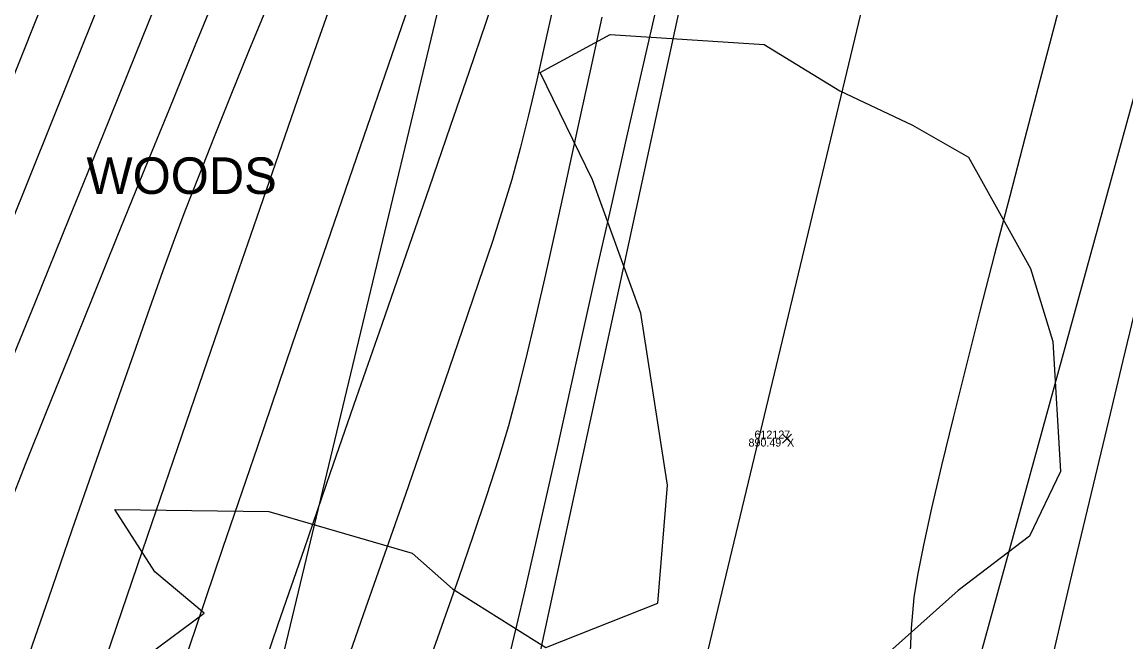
# Model space of a CAD drawing. Extents: x 1957117 to 1971063, y 701601 to 715861.
# Drawn here: x 1963376.25 to 1963424.5, y 706387.49 to 706414.59 of the extents above; entities that cross this region are included whole.
import ezdxf

# ---------------------------------------------------------------- set-up
doc = ezdxf.new("R2010")
doc.units = 0
for name, color, linetype in [('AP_X_Lights', 7, 'Continuous'), ('DT_X_Break_Line', 7, 'Continuous'), ('DT_X_Contour_Major', 7, 'Continuous'), ('DT_X_Contour_Minor', 7, 'Continuous'), ('GE_X_CL_20', 7, 'Continuous'), ('HY_X_Water_Edge', 7, 'Continuous'), ('PV_P_Shoulder', 7, 'Continuous'), ('RS_Raster1', 7, 'Continuous'), ('RW_X_Esmt_RR', 7, 'Continuous'), ('SC_Scratch1', 7, 'Continuous'), ('SC_Shading5', 7, 'Continuous'), ('VG_X_Text', 7, 'Continuous'), ('VG_X_Tree_Line_Rt', 7, 'Continuous')]:
    doc.layers.add(name, color=color, linetype=linetype)

msp = doc.modelspace()

# ---------------------------------------------------------------- linework, layer by layer
at = {"layer": 'AP_X_Lights'}
for p, q in [((1963409.494, 706396.183), (1963409.882, 706396.573)), ((1963409.494, 706396.573), (1963409.882, 706396.183))]:
    msp.add_line(p, q, dxfattribs=at)
at = {"layer": 'DT_X_Break_Line'}
for points in [[(1963248.355, 705747.376), (1963261.829, 705795.923), (1963267.581, 705840.559), (1963287.153, 705892.264), (1963291.083, 705944.763), (1963301.574, 705996.211), (1963311.528, 706039.027), (1963334.717, 706086.75), (1963331.957, 706106.508), (1963348.786, 706182.796), (1963365.664, 706223.934), (1963373.462, 706281.461), (1963387.853, 706330.217), (1963397.264, 706379.501), (1963407.696, 706427.592), (1963426.755, 706477.16), (1963442.136, 706524.014), (1963446.007, 706569.971), (1963489.391, 706666.839), (1963500.526, 706701.536)], [(1963509.92, 706697.686), (1963502.832, 706666.547), (1963464.625, 706568.104), (1963439.113, 706472.593), (1963428.782, 706425.675), (1963415.739, 706378.185), (1963398.991, 706327.191), (1963392.393, 706279.173), (1963377.9, 706227.719), (1963369.87, 706175.335), (1963345.874, 706098.69), (1963341.112, 706081.071), (1963328.328, 706036.261), (1963311.276, 705989.111), (1963300.503, 705940.076), (1963293.199, 705890.767), (1963276.592, 705844.792), (1963268.336, 705791.927), (1963260.722, 705745.719)]]:
    msp.add_lwpolyline(points, dxfattribs=at)
at = {"layer": 'DT_X_Contour_Major'}
for points in [[(1963387.31, 706442.991), (1963386.479, 706440.327), (1963385.732, 706437.97), (1963385.082, 706435.973), (1963384.545, 706434.39), (1963383.905, 706432.647), (1963382.92, 706430.067), (1963381.625, 706426.744), (1963380.061, 706422.771), (1963378.264, 706418.242), (1963376.274, 706413.248), (1963374.129, 706407.883), (1963371.866, 706402.241), (1963369.524, 706396.415), (1963367.142, 706390.496), (1963364.757, 706384.58)], [(1963387.31, 706442.991), (1963386.479, 706440.327), (1963385.732, 706437.97), (1963385.082, 706435.973), (1963384.545, 706434.39), (1963383.905, 706432.647), (1963382.92, 706430.067), (1963381.625, 706426.744), (1963380.061, 706422.771), (1963378.264, 706418.242), (1963376.274, 706413.248), (1963374.129, 706407.883), (1963371.866, 706402.241), (1963369.524, 706396.415), (1963367.142, 706390.496), (1963364.757, 706384.58)], [(1963424.522, 706427.015), (1963424.149, 706425.395), (1963423.812, 706423.96), (1963423.467, 706422.548), (1963423.039, 706420.849), (1963422.539, 706418.904), (1963421.981, 706416.756), (1963421.377, 706414.447), (1963420.741, 706412.018), (1963420.084, 706409.512), (1963419.421, 706406.971), (1963418.763, 706404.436), (1963418.123, 706401.949), (1963417.514, 706399.553), (1963416.95, 706397.29), (1963416.442, 706395.201), (1963416.004, 706393.329), (1963415.648, 706391.716), (1963415.387, 706390.403), (1963415.234, 706389.432), (1963415.11, 706388.084), (1963415.052, 706386.722)], [(1963424.522, 706427.015), (1963424.149, 706425.395), (1963423.812, 706423.96), (1963423.467, 706422.548), (1963423.039, 706420.849), (1963422.539, 706418.904), (1963421.981, 706416.756), (1963421.377, 706414.447), (1963420.741, 706412.018), (1963420.084, 706409.512), (1963419.421, 706406.971), (1963418.763, 706404.436), (1963418.123, 706401.949), (1963417.514, 706399.553), (1963416.95, 706397.29), (1963416.442, 706395.201), (1963416.004, 706393.329), (1963415.648, 706391.716), (1963415.387, 706390.403), (1963415.234, 706389.432), (1963415.11, 706388.084), (1963415.052, 706386.722)], [(1963389.698, 706415.242), (1963388.846, 706412.8), (1963387.864, 706409.974), (1963386.773, 706406.821), (1963385.591, 706403.399), (1963384.34, 706399.765), (1963383.041, 706395.977), (1963381.713, 706392.091), (1963380.376, 706388.166), (1963379.052, 706384.259)], [(1963389.698, 706415.242), (1963388.846, 706412.8), (1963387.864, 706409.974), (1963386.773, 706406.821), (1963385.591, 706403.399), (1963384.34, 706399.765), (1963383.041, 706395.977), (1963381.713, 706392.091), (1963380.376, 706388.166), (1963379.052, 706384.259)], [(1963403.94, 706415.084), (1963403.31, 706412.355), (1963402.674, 706409.561), (1963402.038, 706406.742), (1963401.409, 706403.94), (1963400.796, 706401.194), (1963400.206, 706398.547), (1963399.646, 706396.037), (1963399.125, 706393.707), (1963398.649, 706391.597), (1963398.227, 706389.747), (1963397.866, 706388.199), (1963397.573, 706386.992)], [(1963403.94, 706415.084), (1963403.31, 706412.355), (1963402.674, 706409.561), (1963402.038, 706406.742), (1963401.409, 706403.94), (1963400.796, 706401.194), (1963400.206, 706398.547), (1963399.646, 706396.037), (1963399.125, 706393.707), (1963398.649, 706391.597), (1963398.227, 706389.747), (1963397.866, 706388.199), (1963397.573, 706386.992)]]:
    msp.add_lwpolyline(points, dxfattribs=at)
at = {"layer": 'DT_X_Contour_Minor'}
for points in [[(1963390.055, 706443.837), (1963389.3, 706441.399), (1963388.592, 706439.145), (1963387.942, 706437.114), (1963387.362, 706435.346), (1963386.862, 706433.88), (1963386.308, 706432.363), (1963385.488, 706430.214), (1963384.431, 706427.5), (1963383.166, 706424.291), (1963381.721, 706420.655), (1963380.126, 706416.662), (1963378.409, 706412.381), (1963376.598, 706407.88), (1963374.722, 706403.228), (1963372.81, 706398.494), (1963370.891, 706393.747), (1963368.993, 706389.056), (1963367.145, 706384.49)], [(1963390.055, 706443.837), (1963389.3, 706441.399), (1963388.592, 706439.145), (1963387.942, 706437.114), (1963387.362, 706435.346), (1963386.862, 706433.88), (1963386.308, 706432.363), (1963385.488, 706430.214), (1963384.431, 706427.5), (1963383.166, 706424.291), (1963381.721, 706420.655), (1963380.126, 706416.662), (1963378.409, 706412.381), (1963376.598, 706407.88), (1963374.722, 706403.228), (1963372.81, 706398.494), (1963370.891, 706393.747), (1963368.993, 706389.056), (1963367.145, 706384.49)], [(1963394.717, 706442.917), (1963394.15, 706441.057), (1963393.588, 706439.242), (1963393.036, 706437.494), (1963392.5, 706435.833), (1963391.985, 706434.282), (1963391.498, 706432.861), (1963391.071, 706431.689), (1963390.5, 706430.187), (1963389.799, 706428.391), (1963388.986, 706426.339), (1963388.076, 706424.068), (1963387.086, 706421.616), (1963386.033, 706419.019), (1963384.934, 706416.316), (1963383.803, 706413.543), (1963382.659, 706410.738), (1963381.517, 706407.938), (1963380.393, 706405.18), (1963379.305, 706402.503), (1963378.268, 706399.942), (1963377.3, 706397.536), (1963376.416, 706395.322), (1963375.633, 706393.337)], [(1963394.717, 706442.917), (1963394.15, 706441.057), (1963393.588, 706439.242), (1963393.036, 706437.494), (1963392.5, 706435.833), (1963391.985, 706434.282), (1963391.498, 706432.861), (1963391.071, 706431.689), (1963390.5, 706430.187), (1963389.799, 706428.391), (1963388.986, 706426.339), (1963388.076, 706424.068), (1963387.086, 706421.616), (1963386.033, 706419.019), (1963384.934, 706416.316), (1963383.803, 706413.543), (1963382.659, 706410.738), (1963381.517, 706407.938), (1963380.393, 706405.18), (1963379.305, 706402.503), (1963378.268, 706399.942), (1963377.3, 706397.536), (1963376.416, 706395.322), (1963375.633, 706393.337)], [(1963392.079, 706442.364), (1963391.421, 706440.247), (1963390.794, 706438.257), (1963390.205, 706436.427), (1963389.664, 706434.787), (1963389.18, 706433.371), (1963388.711, 706432.082), (1963388.05, 706430.344), (1963387.217, 706428.203), (1963386.233, 706425.709), (1963385.119, 706422.908), (1963383.893, 706419.848), (1963382.577, 706416.578), (1963381.192, 706413.144), (1963379.756, 706409.596), (1963378.291, 706405.981), (1963376.816, 706402.346), (1963375.352, 706398.74), (1963373.92, 706395.21), (1963372.539, 706391.804), (1963371.23, 706388.571), (1963370.013, 706385.557)], [(1963392.079, 706442.364), (1963391.421, 706440.247), (1963390.794, 706438.257), (1963390.205, 706436.427), (1963389.664, 706434.787), (1963389.18, 706433.371), (1963388.711, 706432.082), (1963388.05, 706430.344), (1963387.217, 706428.203), (1963386.233, 706425.709), (1963385.119, 706422.908), (1963383.893, 706419.848), (1963382.577, 706416.578), (1963381.192, 706413.144), (1963379.756, 706409.596), (1963378.291, 706405.981), (1963376.816, 706402.346), (1963375.352, 706398.74), (1963373.92, 706395.21), (1963372.539, 706391.804), (1963371.23, 706388.571), (1963370.013, 706385.557)], [(1963393.693, 706416.887), (1963392.405, 706413.152), (1963391.019, 706409.128), (1963389.562, 706404.887), (1963388.057, 706400.499), (1963386.531, 706396.037), (1963385.01, 706391.57), (1963383.518, 706387.171)], [(1963393.693, 706416.887), (1963392.405, 706413.152), (1963391.019, 706409.128), (1963389.562, 706404.887), (1963388.057, 706400.499), (1963386.531, 706396.037), (1963385.01, 706391.57), (1963383.518, 706387.171)], [(1963397.094, 706416.263), (1963396.51, 706414.524), (1963395.794, 706412.426), (1963394.965, 706410.014), (1963394.04, 706407.335), (1963393.035, 706404.436), (1963391.969, 706401.362), (1963390.858, 706398.16), (1963389.72, 706394.875), (1963388.573, 706391.555), (1963387.432, 706388.244), (1963386.317, 706384.99)], [(1963397.094, 706416.263), (1963396.51, 706414.524), (1963395.794, 706412.426), (1963394.965, 706410.014), (1963394.04, 706407.335), (1963393.035, 706404.436), (1963391.969, 706401.362), (1963390.858, 706398.16), (1963389.72, 706394.875), (1963388.573, 706391.555), (1963387.432, 706388.244), (1963386.317, 706384.99)], [(1963386.954, 706415.273), (1963386.147, 706413.297), (1963385.371, 706411.385), (1963384.641, 706409.566), (1963383.969, 706407.867), (1963383.368, 706406.317), (1963382.853, 706404.945), (1963382.404, 706403.708), (1963381.818, 706402.066), (1963381.11, 706400.066), (1963380.298, 706397.754), (1963379.397, 706395.175), (1963378.424, 706392.376), (1963377.395, 706389.402), (1963376.327, 706386.299)], [(1963386.954, 706415.273), (1963386.147, 706413.297), (1963385.371, 706411.385), (1963384.641, 706409.566), (1963383.969, 706407.867), (1963383.368, 706406.317), (1963382.853, 706404.945), (1963382.404, 706403.708), (1963381.818, 706402.066), (1963381.11, 706400.066), (1963380.298, 706397.754), (1963379.397, 706395.175), (1963378.424, 706392.376), (1963377.395, 706389.402), (1963376.327, 706386.299)], [(1963399.464, 706415.274), (1963399.106, 706413.633), (1963398.746, 706412.04), (1963398.385, 706410.511), (1963398.021, 706409.061), (1963397.653, 706407.708), (1963397.294, 706406.519), (1963396.806, 706405), (1963396.204, 706403.194), (1963395.506, 706401.143), (1963394.728, 706398.888), (1963393.888, 706396.472), (1963393.001, 706393.936), (1963392.085, 706391.322), (1963391.158, 706388.672), (1963390.234, 706386.028)], [(1963399.464, 706415.274), (1963399.106, 706413.633), (1963398.746, 706412.04), (1963398.385, 706410.511), (1963398.021, 706409.061), (1963397.653, 706407.708), (1963397.294, 706406.519), (1963396.806, 706405), (1963396.204, 706403.194), (1963395.506, 706401.143), (1963394.728, 706398.888), (1963393.888, 706396.472), (1963393.001, 706393.936), (1963392.085, 706391.322), (1963391.158, 706388.672), (1963390.234, 706386.028)], [(1963401.598, 706414.794), (1963401.085, 706412.457), (1963400.577, 706410.131), (1963400.077, 706407.849), (1963399.591, 706405.644), (1963399.122, 706403.55), (1963398.675, 706401.599), (1963398.253, 706399.824), (1963397.861, 706398.26), (1963397.504, 706396.938), (1963397.071, 706395.488), (1963396.555, 706393.878), (1963395.972, 706392.139), (1963395.338, 706390.303), (1963394.669, 706388.404), (1963393.981, 706386.472)], [(1963401.598, 706414.794), (1963401.085, 706412.457), (1963400.577, 706410.131), (1963400.077, 706407.849), (1963399.591, 706405.644), (1963399.122, 706403.55), (1963398.675, 706401.599), (1963398.253, 706399.824), (1963397.861, 706398.26), (1963397.504, 706396.938), (1963397.071, 706395.488), (1963396.555, 706393.878), (1963395.972, 706392.139), (1963395.338, 706390.303), (1963394.669, 706388.404), (1963393.981, 706386.472)], [(1963421.301, 706386.857), (1963421.594, 706388.1), (1963421.847, 706389.162), (1963422.203, 706390.658), (1963422.649, 706392.527), (1963423.171, 706394.713), (1963423.754, 706397.154), (1963424.384, 706399.792), (1963425.048, 706402.568)], [(1963421.301, 706386.857), (1963421.594, 706388.1), (1963421.847, 706389.162), (1963422.203, 706390.658), (1963422.649, 706392.527), (1963423.171, 706394.713), (1963423.754, 706397.154), (1963424.384, 706399.792), (1963425.048, 706402.568)]]:
    msp.add_lwpolyline(points, dxfattribs=at)
at = {"layer": 'GE_X_CL_20'}
msp.add_lwpolyline([(1963418.3, 706437.397), (1962895.621, 704261.062)], dxfattribs=at)
at = {"layer": 'HY_X_Water_Edge'}
msp.add_spline([(1963191.723, 701994.048), (1963062.047, 702441.167), (1962863.491, 703169.356), (1962827.53, 703438.691), (1962823.213, 703537.412), (1962817.962, 703593.874), (1962817.97, 703697.316), (1962828.582, 703804.235), (1962836.461, 703844.734), (1962850.687, 703896.004), (1962867.251, 703938.846), (1962873.848, 703992.355), (1962884.135, 704091.371), (1962891.241, 704140.854), (1962897.382, 704180.529), (1962905.467, 704230.979), (1962943.949, 704328.022), (1962948.537, 704378.842), (1962964.114, 704426.264), (1963004.885, 704570.73), (1963042.054, 704716.522), (1963062.038, 704814.417), (1963072.171, 704860.237), (1963090.023, 704956.798), (1963107.066, 705031.783), (1963133.773, 705105.742), (1963148.685, 705206.74), (1963175.48, 705301.059), (1963191.635, 705353.417), (1963210.988, 705447.286), (1963219.532, 705497.27), (1963230.124, 705549.475), (1963251.052, 705591.159), (1963275.289, 705693.429), (1963292.982, 705784.032), (1963302.841, 705839.645), (1963335.126, 705936.766), (1963359.752, 706046.75), (1963389.133, 706177.299), (1963417.827, 706273.456), (1963475.868, 706451.902), (1963533.782, 706640.53), (1963553.86, 706696.984), (1963580.184, 706715.425), (1963609.172, 706718.73), (1963617.062, 706714.691), (1963619.447, 706694.678), (1963564.282, 706533.07), (1963531.853, 706395.229), (1963434.4, 706006.96), (1963354.09, 705679.186), (1963237.513, 705206.07), (1963167.369, 704892.962), (1963059.145, 704434.176), (1962907.914, 703908.742), (1962877.458, 703703.326), (1962898.357, 703412.121), (1962942.65, 703052.267), (1963048.963, 702674.866), (1963191.468, 702189.666), (1963245.396, 702019.832)], degree=3, dxfattribs=at)
at = {"layer": 'RW_X_Esmt_RR'}
msp.add_lwpolyline([(1962866.45, 704268.068), (1963123.345, 705337.727), (1963135.496, 705336.937), (1963400.797, 706441.601)], dxfattribs=at)
at = {"layer": 'SC_Shading5'}
for points in [[(1963026.912, 704294.121), (1963138.818, 704737.794), (1963251.679, 705213.963), (1963374.306, 705730.111), (1963454.783, 706045.593), (1963517.244, 706296.713), (1963562.763, 706479.256), (1963580.13, 706553.799), (1963589.678, 706586.994)], [(1963609.915, 706579.703), (1963587.283, 706499.153), (1963552.056, 706354.005), (1963480.911, 706069.234), (1963357.401, 705576.869), (1963272.751, 705226.931), (1963210.247, 704956.481), (1963044.97, 704288.881)]]:
    msp.add_spline(points, degree=3, dxfattribs=at)
at = {"layer": 'VG_X_Tree_Line_Rt'}
for points in [[(1963381.767, 706386.932), (1963378.443, 706384.822), (1963381.767, 706386.932), (1963384.207, 706388.748), (1963382.044, 706390.553), (1963380.299, 706393.272), (1963387.032, 706393.185), (1963393.305, 706391.374), (1963395.066, 706389.812), (1963399.138, 706387.246), (1963404.04, 706389.179), (1963404.468, 706394.346), (1963403.29, 706401.854), (1963401.185, 706407.689), (1963398.895, 706412.377), (1963401.95, 706414.045)], [(1963401.95, 706414.045), (1963408.685, 706413.599), (1963411.998, 706411.575), (1963415.18, 706410.072), (1963417.625, 706408.676), (1963420.339, 706403.815), (1963421.311, 706400.624), (1963421.638, 706394.937), (1963420.282, 706392.116), (1963417.174, 706389.735), (1963412.957, 706385.973)]]:
    msp.add_lwpolyline(points, dxfattribs=at)

# ---------------------------------------------------------------- texts
at = {"layer": 'PV_P_Shoulder'}
msp.add_text('890.49', height=0.35, dxfattribs=at).set_placement((1963408.004, 706396.028))
at = {"layer": 'RS_Raster1'}
msp.add_text('612127', height=0.35, dxfattribs=at).set_placement((1963408.264, 706396.378))
at = {"layer": 'SC_Scratch1'}
msp.add_text('X', height=0.35, dxfattribs=at).set_placement((1963409.688, 706396.028))
at = {"layer": 'VG_X_Text'}
msp.add_text('WOODS', height=1.6, dxfattribs=at).set_placement((1963379.062, 706407.071))

doc.saveas('drawing.dxf')
